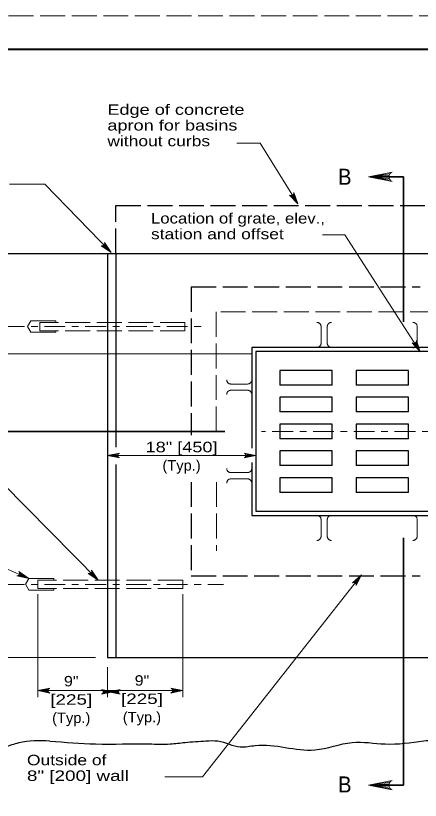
# Model space of a CAD drawing. Extents: x 1083.1 to 1117.1, y 719.4 to 763.4.
# Drawn here: x 1089.96 to 1096.01, y 751.62 to 763.35 of the extents above; entities that cross this region are included whole.
import ezdxf
from ezdxf.enums import TextEntityAlignment as Align

# ---------------------------------------------------------------- set-up
doc = ezdxf.new("R2010")
doc.units = 0
doc.header["$LTSCALE"] = 0.062
doc.linetypes.add('DOT_DASHED', pattern=[7.7, 5, -1.2, 0.3, -1.2])
doc.linetypes.add('LONG_DASHED', pattern=[7.5, 6, -1.5])
doc.layers.add('1', color=7, linetype='Continuous', lineweight=13)

msp = doc.modelspace()

# ---------------------------------------------------------------- linework, layer by layer
at = {"layer": '1', "lineweight": 25}
for p, q in [((1085.12642, 762.85408), (1116.62642, 762.85408)), ((1089.198, 759.79842), (1102.43125, 759.79842)), ((1091.32908, 759.79842), (1091.32908, 753.75592)), ((1091.45408, 759.79842), (1091.45408, 756.90225)), ((1093.48525, 758.39233), (1093.48525, 756.88583)), ((1095.56592, 758.39233), (1093.48525, 758.39233)), ((1098.52517, 758.39233), (1095.56592, 758.39233)), ((1093.90583, 758.04875), (1093.90583, 757.83)), ((1095.045, 758.04875), (1095.045, 757.83)), ((1094.687, 757.83), (1093.90583, 757.83)), ((1095.82625, 757.83), (1095.045, 757.83)), ((1093.90583, 757.64733), (1093.90583, 757.42858)), ((1095.045, 757.64733), (1095.045, 757.42858)), ((1094.687, 757.42858), (1093.90583, 757.42858)), ((1095.82625, 757.42858), (1095.045, 757.42858)), ((1093.90583, 757.24583), (1093.90583, 757.02717)), ((1095.82625, 757.24583), (1095.045, 757.24583)), ((1095.045, 757.24583), (1095.045, 757.02717)), ((1094.687, 757.02717), (1093.90583, 757.02717)), ((1095.82625, 757.02717), (1095.045, 757.02717)), ((1093.90583, 756.84442), (1093.90583, 756.62567)), ((1095.045, 756.84442), (1095.045, 756.62567)), ((1093.48525, 756.67167), (1093.48525, 755.88067)), ((1094.687, 756.62567), (1093.90583, 756.62567)), ((1095.82625, 756.62567), (1095.045, 756.62567)), ((1093.90583, 756.443), (1093.90583, 756.22425)), ((1095.045, 756.443), (1095.045, 756.22425)), ((1094.687, 756.22425), (1093.90583, 756.22425)), ((1095.82625, 756.22425), (1095.045, 756.22425)), ((1091.32908, 753.75592), (1100.68133, 753.75592))]:
    msp.add_line(p, q, dxfattribs=at)
at = {"layer": '1'}
for p, q in [((1095.54992, 760.9895), (1095.22925, 760.94467)), ((1095.539, 760.96733), (1095.22925, 760.94467)), ((1095.53575, 760.94467), (1095.22925, 760.94467)), ((1095.54142, 760.91583), (1095.22925, 760.94467)), ((1095.55367, 760.89508), (1095.22925, 760.94467)), ((1094.07142, 760.66283), (1094.175, 760.5385)), ((1094.08367, 760.66408), (1094.175, 760.5385)), ((1094.09425, 760.66867), (1094.175, 760.5385)), ((1094.10492, 760.67867), (1094.175, 760.5385)), ((1094.11058, 760.68933), (1094.175, 760.5385)), ((1091.25325, 759.91108), (1091.38075, 759.81133)), ((1091.265, 759.91492), (1091.38075, 759.81133)), ((1091.27425, 759.92158), (1091.38075, 759.81133)), ((1091.28267, 759.93358), (1091.38075, 759.81133)), ((1091.28592, 759.94525), (1091.38075, 759.81133)), ((1095.905, 758.45233), (1096.005, 758.32508)), ((1095.91733, 758.45325), (1096.005, 758.32508)), ((1095.92792, 758.4575), (1096.005, 758.32508)), ((1095.93892, 758.46725), (1096.005, 758.32508)), ((1095.94483, 758.47775), (1096.005, 758.32508)), ((1093.48525, 758.29858), (1089.25483, 758.29858)), ((1091.48942, 756.79942), (1091.32908, 756.777)), ((1091.484, 756.78833), (1091.32908, 756.777)), ((1093.38742, 756.79942), (1093.54775, 756.777)), ((1093.39292, 756.78833), (1093.54775, 756.777)), ((1091.48233, 756.777), (1091.32908, 756.777)), ((1091.48517, 756.76258), (1091.32908, 756.777)), ((1091.49133, 756.75225), (1091.32908, 756.777)), ((1093.38558, 756.75225), (1093.54775, 756.777)), ((1093.39167, 756.76258), (1093.54775, 756.777)), ((1093.3945, 756.777), (1093.54775, 756.777)), ((1090.14967, 754.93542), (1088.6665, 755.58675)), ((1090.01125, 755.0235), (1090.14967, 754.93542)), ((1091.08217, 755.0215), (1091.18933, 754.912)), ((1091.0905, 755.03358), (1091.18933, 754.912)), ((1091.09358, 755.04525), (1091.18933, 754.912)), ((1089.99392, 754.9795), (1090.14967, 754.93542)), ((1090.00333, 754.9875), (1090.14967, 754.93542)), ((1090.00942, 754.99717), (1090.14967, 754.93542)), ((1090.01267, 755.0115), (1090.14967, 754.93542)), ((1091.06117, 755.01083), (1091.18933, 754.912)), ((1091.07292, 755.01475), (1091.18933, 754.912)), ((1095.00708, 754.87883), (1095.12533, 754.9925)), ((1095.019, 754.87733), (1095.12533, 754.9925)), ((1095.03217, 754.87083), (1095.12533, 754.9925)), ((1095.04017, 754.86267), (1095.12533, 754.9925)), ((1095.04567, 754.85158), (1095.12533, 754.9925)), ((1090.28758, 754.70367), (1090.28758, 753.16042)), ((1092.45408, 754.70367), (1092.45408, 753.16042)), ((1091.14975, 753.75592), (1087.94617, 753.75592)), ((1091.32908, 753.61017), (1091.32908, 753.16042)), ((1090.44792, 753.28183), (1090.28758, 753.25942)), ((1090.44242, 753.27075), (1090.28758, 753.25942)), ((1090.28758, 753.25942), (1092.45408, 753.25942)), ((1090.44083, 753.25942), (1090.28758, 753.25942)), ((1090.44367, 753.245), (1090.28758, 753.25942)), ((1090.44975, 753.23467), (1090.28758, 753.25942)), ((1091.25733, 753.26417), (1091.41767, 753.24175)), ((1091.50133, 753.26417), (1091.341, 753.24175)), ((1092.29183, 753.23467), (1092.45408, 753.25942)), ((1092.29375, 753.28183), (1092.45408, 753.25942)), ((1092.298, 753.245), (1092.45408, 753.25942)), ((1092.29917, 753.27075), (1092.45408, 753.25942)), ((1092.30083, 753.25942), (1092.45408, 753.25942)), ((1091.25542, 753.21692), (1091.41767, 753.24175)), ((1091.26158, 753.22733), (1091.41767, 753.24175)), ((1091.26275, 753.253), (1091.41767, 753.24175)), ((1091.26442, 753.24175), (1091.41767, 753.24175)), ((1091.49592, 753.253), (1091.341, 753.24175)), ((1091.49425, 753.24175), (1091.341, 753.24175)), ((1091.49708, 753.22733), (1091.341, 753.24175)), ((1091.50325, 753.21692), (1091.341, 753.24175)), ((1095.54992, 751.89025), (1095.22925, 751.84542)), ((1095.539, 751.86808), (1095.22925, 751.84542)), ((1095.53575, 751.84542), (1095.22925, 751.84542)), ((1095.54142, 751.81658), (1095.22925, 751.84542)), ((1095.55367, 751.79583), (1095.22925, 751.84542))]:
    msp.add_line(p, q, dxfattribs=at)
at = {"layer": '1', "lineweight": 35}
for p, q in [((1095.75525, 760.94467), (1095.27092, 760.94467)), ((1095.75525, 758.77625), (1095.75525, 760.94467)), ((1093.0845, 757.1365), (1088.56, 757.1365)), ((1095.75525, 751.84542), (1095.75525, 755.54467)), ((1095.75525, 751.84542), (1095.27092, 751.84542))]:
    msp.add_line(p, q, dxfattribs=at)
at = {"layer": '1', "linetype": 'LONG_DASHED', "lineweight": 25}
for p, q in [((1091.45408, 760.517), (1100.55633, 760.517)), ((1091.45408, 759.79842), (1091.45408, 760.517)), ((1092.57908, 759.2985), (1096.00525, 759.2985)), ((1092.57908, 759.2985), (1092.57908, 757.081)), ((1092.57908, 756.379), (1092.57908, 754.9745)), ((1092.57908, 754.9745), (1096.00525, 754.9745))]:
    msp.add_line(p, q, dxfattribs=at)
at = {"layer": '1', "linetype": 'LONG_DASHED'}
for p, q in [((1099.05642, 758.9235), (1092.954, 758.9235)), ((1092.954, 758.9235), (1092.95517, 757.05858)), ((1090.55592, 758.79075), (1090.55592, 758.76733)), ((1094.521, 758.45483), (1094.521, 758.70483)), ((1094.61467, 758.45483), (1094.61467, 758.70483)), ((1095.95842, 758.45483), (1095.95842, 758.70483)), ((1090.55592, 758.64233), (1090.55592, 758.61892)), ((1093.42275, 757.84558), (1093.17275, 757.84558)), ((1093.42275, 757.75183), (1093.17275, 757.75183)), ((1093.42275, 756.52108), (1093.17275, 756.52108)), ((1093.42275, 756.42733), (1093.17275, 756.42733)), ((1092.95558, 756.37925), (1092.95617, 755.34942)), ((1094.521, 755.81808), (1094.521, 755.56808)), ((1094.61467, 755.81808), (1094.61467, 755.56808)), ((1095.95842, 755.81808), (1095.95842, 755.56808)), ((1090.52467, 754.912), (1090.52467, 754.93542)), ((1090.52467, 754.76358), (1090.52467, 754.787))]:
    msp.add_line(p, q, dxfattribs=at)
at = {"layer": '1', "linetype": 'DOT_DASHED'}
for p, q in [((1087.94617, 758.70483), (1092.74192, 758.70483)), ((1098.37175, 757.1365), (1093.6325, 757.1365)), ((1087.94617, 754.84875), (1093.06475, 754.84875))]:
    msp.add_line(p, q, dxfattribs=at)
at = {"layer": '1', "linetype": 'LONG_DASHED'}
msp.add_lwpolyline([(1083.12642, 741.35408), (1117.12642, 741.35408), (1117.12642, 763.35408), (1083.12642, 763.35408)], close=True, dxfattribs=at)
at = {"layer": '1', "lineweight": 40}
msp.add_lwpolyline([(1085.12642, 762.85408), (1116.62642, 762.85408), (1116.62642, 741.85408), (1085.12642, 741.85408)], close=True, dxfattribs=at)
msp.add_lwpolyline([(1085.12642, 762.85408), (1116.62642, 762.85408), (1116.62642, 741.85408), (1085.12642, 741.85408)], close=True, dxfattribs=at)
at = {"layer": '1'}
for points in [[(1094.175, 760.5385), (1093.61183, 761.44625), (1093.25983, 761.44625)], [(1095.58342, 760.87383), (1095.22925, 760.94467), (1095.58342, 761.0155)], [(1091.38075, 759.81133), (1090.39117, 760.83558), (1089.86325, 760.83558)], [(1094.11175, 760.70758), (1094.175, 760.5385), (1094.0515, 760.67025)], [(1096.005, 758.32508), (1094.87892, 760.07633), (1094.54458, 760.07633)], [(1091.28317, 759.96333), (1091.38075, 759.81133), (1091.23225, 759.91408)], [(1090.55592, 758.79075), (1090.18092, 758.79075), (1090.13133, 758.70483), (1090.18092, 758.61892), (1090.55592, 758.61892)], [(1095.9465, 758.496), (1096.005, 758.32508), (1095.88533, 758.46033)], [(1091.50617, 756.74158), (1091.32908, 756.777), (1091.50617, 756.81242)], [(1093.37067, 756.74158), (1093.54775, 756.777), (1093.37067, 756.81242)], [(1091.32908, 756.777), (1092.65967, 756.777), (1093.54775, 756.777)], [(1091.18933, 754.912), (1089.75767, 756.3625), (1088.52575, 756.3625)], [(1090.00192, 755.03917), (1090.14967, 754.93542), (1089.97333, 754.97442)], [(1091.09075, 755.06325), (1091.18933, 754.912), (1091.04017, 755.01375)], [(1090.52467, 754.76358), (1090.14967, 754.76358), (1090.10008, 754.8495), (1090.14967, 754.93542), (1090.52467, 754.93542)], [(1095.12533, 754.9925), (1092.7495, 751.972), (1092.18633, 751.972)], [(1094.98958, 754.87342), (1095.12533, 754.9925), (1095.04583, 754.83042)], [(1090.46467, 753.224), (1090.28758, 753.25942), (1090.46467, 753.29483)], [(1091.24058, 753.20633), (1091.41767, 753.24175), (1091.24058, 753.27708)], [(1091.51808, 753.20633), (1091.341, 753.24175), (1091.51808, 753.27708)], [(1092.277, 753.224), (1092.45408, 753.25942), (1092.277, 753.29483)], [(1095.58342, 751.77458), (1095.22925, 751.84542), (1095.58342, 751.91625)]]:
    msp.add_lwpolyline(points, dxfattribs=at)
at = {"layer": '1', "linetype": 'LONG_DASHED'}
for points in [[(1092.48533, 758.64233), (1092.48533, 758.76733), (1090.31883, 758.76733)], [(1092.48533, 758.64233), (1090.31883, 758.64233), (1090.31883, 758.76733)], [(1092.45408, 754.912), (1092.45408, 754.787), (1090.28758, 754.787)], [(1092.45408, 754.912), (1090.28758, 754.912), (1090.28758, 754.787)]]:
    msp.add_lwpolyline(points, dxfattribs=at)
at = {"layer": '1', "lineweight": 25}
for points in [[(1093.54775, 758.32983), (1093.54775, 755.94317), (1098.46267, 755.94317), (1098.46267, 758.32983)], [(1098.46267, 758.32983), (1096.00333, 758.32983), (1093.54775, 758.32983)], [(1094.687, 757.83), (1094.687, 758.04875), (1093.90583, 758.04875)], [(1095.82625, 757.83), (1095.82625, 758.04875), (1095.045, 758.04875)], [(1094.687, 757.42858), (1094.687, 757.64733), (1093.90583, 757.64733)], [(1095.82625, 757.42858), (1095.82625, 757.64733), (1095.045, 757.64733)], [(1094.687, 757.02717), (1094.687, 757.24583), (1093.90583, 757.24583)], [(1095.82625, 757.02717), (1095.82625, 757.20833), (1095.82625, 757.24583)], [(1094.687, 756.62567), (1094.687, 756.84442), (1093.90583, 756.84442)], [(1095.82625, 756.62567), (1095.82625, 756.84442), (1095.045, 756.84442)], [(1091.45408, 756.63983), (1091.45408, 754.29617), (1091.45408, 753.75592)], [(1094.687, 756.22425), (1094.687, 756.443), (1093.90583, 756.443)], [(1095.82625, 756.22425), (1095.82625, 756.443), (1095.045, 756.443)], [(1093.48525, 755.88067), (1096.42658, 755.88067), (1098.52517, 755.88067)]]:
    msp.add_lwpolyline(points, dxfattribs=at)
at = {"layer": '1'}
for centre, radius, start, end in [((1095.61201, 760.94471), 0.07644, 112.08782, 247.91395), ((1094.07407, 760.70108), 0.03822, 233.90118, 9.72731), ((1091.24775, 759.94898), 0.03822, 246.102, 21.92813), ((1095.90866, 758.49048), 0.03822, 232.29724, 8.12337), ((1091.52049, 756.77706), 0.03822, 112.08782, 247.91395), ((1093.35638, 756.77706), 0.03822, 292.08605, 67.91218), ((1089.97452, 755.01252), 0.03822, 268.30769, 44.13382), ((1091.05544, 755.04871), 0.03822, 246.47514, 22.30127), ((1095.00902, 754.84055), 0.03822, 344.65059, 120.47672), ((1090.47895, 753.25946), 0.03822, 112.08782, 247.91395), ((1091.22627, 753.24175), 0.03822, 292.08605, 67.91218), ((1091.53241, 753.24175), 0.03822, 112.08782, 247.91395), ((1092.26268, 753.25946), 0.03822, 292.08605, 67.91218), ((1095.61201, 751.84549), 0.07644, 112.08782, 247.91395)]:
    msp.add_arc(centre, radius, start, end, dxfattribs=at)
at = {"layer": '1', "linetype": 'LONG_DASHED'}
for centre, major_axis, ratio, start_param, end_param in [((1094.45846, 758.70481), (0.0625, 0), 0.999895, 6.28318531, 7.85398163), ((1094.6772, 758.70481), (-0.0625, 0), 0.999895, 4.71238898, 6.28318531), ((1095.8959, 758.70481), (0.0625, 0), 0.999895, 6.28318531, 7.85398163), ((1094.45846, 758.45485), (-0.0625, 0), 0.999895, 1.57079633, 3.14159265), ((1094.6772, 758.45485), (-0.0625, 0), 0.999895, 6.28318531, 7.85398163), ((1095.8959, 758.45485), (0, -0.06724), 0.929459, 0, 1.57079633), ((1093.17277, 757.9081), (-0.0625, 0), 0.999895, 6.28318531, 7.85398163), ((1093.42276, 757.9081), (-0.0625, 0), 0.999895, 1.57079633, 3.14159265), ((1093.17277, 757.68938), (-0.0625, 0), 0.999895, 4.71238898, 6.28318531), ((1093.42276, 757.68938), (0.0625, 0), 0.999895, 6.28318531, 7.85398163), ((1093.17277, 756.58355), (-0.0625, 0), 0.999895, 6.28318531, 7.85398163), ((1093.42276, 756.58355), (0.0625, 0), 0.999895, 4.71238898, 6.28318531), ((1093.17277, 756.36483), (0.0625, 0), 0.999895, 1.57079633, 3.14159265), ((1093.42276, 756.36483), (0.0625, 0), 0.999895, 6.28318531, 7.85398163), ((1094.45846, 755.81808), (0.0625, 0), 0.999895, 6.28318531, 7.85398163), ((1094.6772, 755.81808), (-0.0625, 0), 0.999895, 4.71238898, 6.28318531), ((1095.8959, 755.81808), (0.0625, 0), 0.999895, 6.28318531, 7.85398163), ((1094.45846, 755.56812), (-0.0625, 0), 0.999895, 1.57079633, 3.14159265), ((1094.6772, 755.56812), (-0.0625, 0), 0.999895, 6.28318531, 7.85398163), ((1095.8959, 755.56812), (-0.0625, 0), 0.999895, 1.57079633, 3.14159265)]:
    msp.add_ellipse(centre, major_axis=major_axis, ratio=ratio, start_param=start_param, end_param=end_param, dxfattribs=at)
at = {"layer": '1', "lineweight": 25}
for points in [[(1090.46658, 752.50608), (1090.00083, 752.4775), (1089.78958, 752.41975), (1089.67442, 752.41975), (1089.59758, 752.439), (1089.444, 752.40058), (1089.30967, 752.41975), (1089.198, 752.53517)], [(1090.46658, 752.50608), (1091.14975, 752.46233), (1091.953, 752.46233), (1092.26533, 752.46233), (1092.48842, 752.48467), (1092.80083, 752.507), (1092.97925, 752.507), (1093.31392, 752.41758), (1093.537, 752.44), (1094.42942, 752.37292), (1094.98717, 752.48467), (1095.478, 752.46233), (1096.05808, 752.507), (1096.32583, 752.52933), (1096.68267, 752.48467), (1097.32975, 752.41758), (1097.95442, 752.39525), (1098.62367, 752.46233), (1099.56075, 752.37292), (1100.02917, 752.41758), (1100.65392, 752.46233), (1101.16708, 752.46233), (1101.85867, 752.44), (1102.28258, 752.44), (1102.571, 752.50608)]]:
    msp.add_spline(points, degree=3, dxfattribs=at)

# ---------------------------------------------------------------- texts
at = {"layer": '1'}
for s, height, width, p in [('Edge of concrete', 0.156, 1.3, (1091.326, 761.87158)), ('apron for basins', 0.156, 1.3, (1091.326, 761.63692)), ('without curbs', 0.156, 1.25, (1091.326, 761.40225)), ('B', 0.24, 0.95, (1094.77417, 760.8255)), ('Location of grate, elev.,', 0.156, 1.2, (1091.97792, 760.24583)), ('station and offset', 0.156, 1.25, (1091.97792, 760.01117)), ('Outside of', 0.156, 1.25, (1090.12383, 752.14392)), ('8" [200] wall', 0.156, 1.35, (1090.12383, 751.90925)), ('B', 0.24, 0.95, (1094.77417, 751.73633))]:
    msp.add_text(s, height=height, dxfattribs=dict(at, width=width)).set_placement(p)
for s, width, p in [('18" [450]', 1.3, (1092.43571, 756.82492)), ('(Typ.)', 1.05, (1092.43579, 756.55083)), ('9"', 1.15, (1090.78617, 753.32317)), ('9"', 1.15, (1091.84317, 753.33392)), ('[225]', 1.35, (1090.78617, 753.04908)), ('[225]', 1.35, (1091.84317, 753.05983)), ('(Typ.)', 1.05, (1090.78621, 752.775)), ('(Typ.)', 1.05, (1091.84321, 752.78575))]:
    msp.add_text(s, height=0.156, dxfattribs=dict(at, width=width)).set_placement(p, align=Align.CENTER)

doc.saveas('drawing.dxf')
